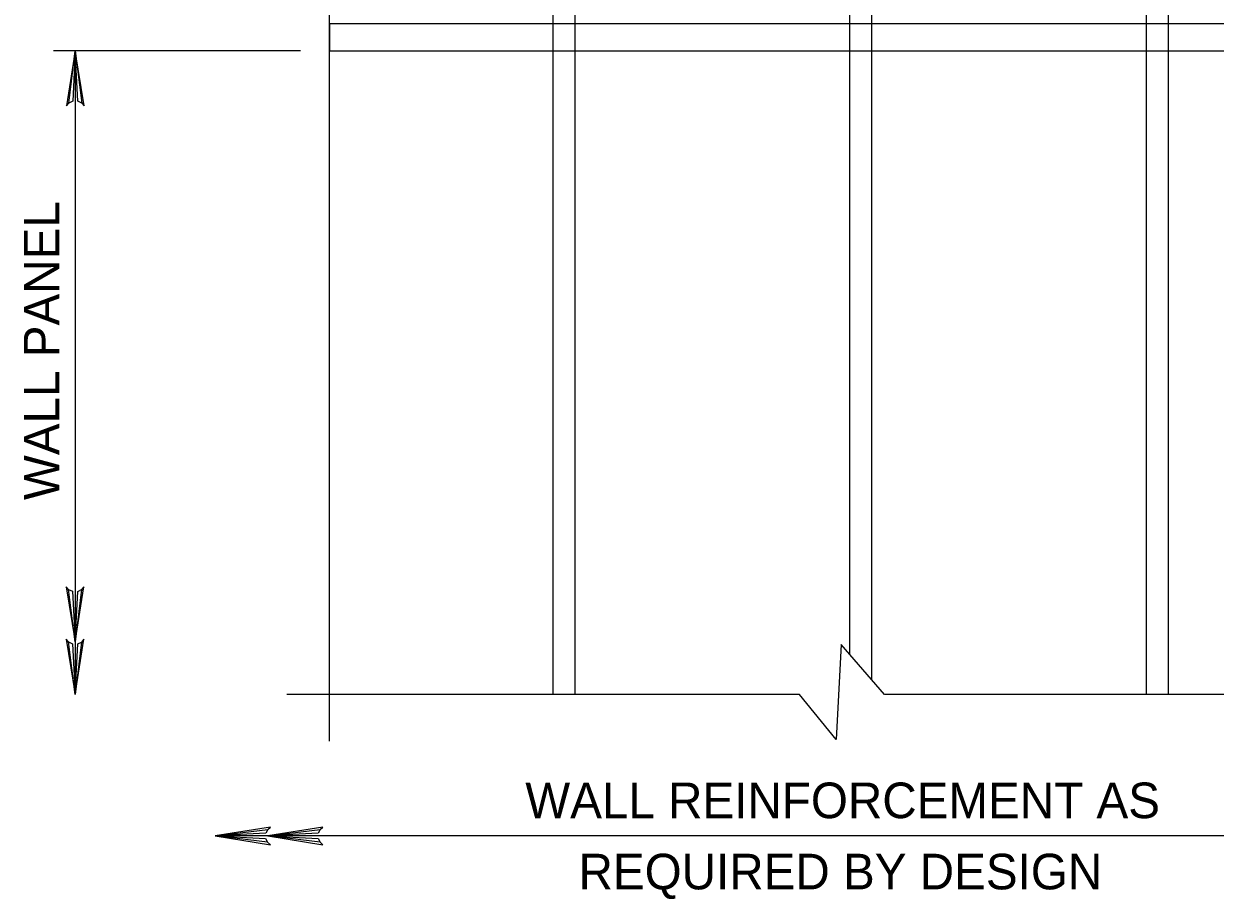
# Model space of a CAD drawing. Extents: x 641328 to 643024, y 298283 to 300065.
# Drawn here: x 642558.5 to 642658.9, y 299585.6 to 299659.4 of the extents above; entities that cross this region are included whole.
import ezdxf

# ---------------------------------------------------------------- set-up
doc = ezdxf.new("R2010")
doc.units = 0
doc.layers.add('2', color=7, linetype='Continuous')
doc.layers.add('63', color=7, linetype='Continuous')

msp = doc.modelspace()

# ---------------------------------------------------------------- linework, layer by layer
at = {"layer": '2'}
for p, q in [((642584.3, 299598.94), (642584.3, 299679.4)), ((642603.12, 299675.03), (642603.12, 299602.89)), ((642604.97, 299675.03), (642604.97, 299602.89)), ((642628.12, 299675.03), (642628.12, 299606.29)), ((642629.97, 299675.03), (642629.97, 299604.14)), ((642653.12, 299675.03), (642653.12, 299602.89)), ((642654.97, 299675.03), (642654.97, 299602.89)), ((642687.27, 299659.41), (642584.3, 299659.41)), ((642584.3, 299659.41), (642584.3, 299657.15)), ((642581.86, 299657.15), (642561.03, 299657.15)), ((642584.3, 299657.15), (642687.27, 299657.15)), ((642584.3, 299657.15), (642687.27, 299657.15)), ((642623.91, 299602.89), (642580.69, 299602.89)), ((642692.13, 299602.89), (642631.06, 299602.89))]:
    msp.add_line(p, q, dxfattribs=at)
at = {"layer": '63'}
for p, q in [((642562.86, 299657.15), (642562.86, 299602.89)), ((642627.41, 299607.11), (642626.99, 299599.08)), ((642631.06, 299602.89), (642627.41, 299607.11)), ((642626.99, 299599.08), (642623.91, 299602.89)), ((642679.97, 299590.96), (642574.65, 299590.96))]:
    msp.add_line(p, q, dxfattribs=at)
for points in [[(642563.41, 299652.72), (642563.09, 299652.89), (642562.86, 299657.15), (642563.41, 299652.72), (642563.61, 299652.49), (642562.86, 299657.15), (642562.65, 299652.89), (642562.33, 299652.73), (642562.86, 299657.15), (642562.12, 299652.49), (642562.33, 299652.73)], [(642562.3, 299611.74), (642562.62, 299611.58), (642562.86, 299607.31), (642562.3, 299611.74), (642562.11, 299611.97), (642562.86, 299607.31), (642563.07, 299611.57), (642563.38, 299611.73), (642562.86, 299607.31), (642563.6, 299611.97), (642563.38, 299611.73)], [(642562.3, 299607.31), (642562.62, 299607.15), (642562.86, 299602.89), (642562.3, 299607.31), (642562.11, 299607.54), (642562.86, 299602.89), (642563.07, 299607.15), (642563.38, 299607.3), (642562.86, 299602.89), (642563.6, 299607.54), (642563.38, 299607.3)], [(642579.08, 299591.51), (642578.92, 299591.19), (642574.65, 299590.96), (642579.08, 299591.51), (642579.31, 299591.71), (642574.65, 299590.96), (642578.91, 299590.75), (642579.07, 299590.43), (642574.65, 299590.96), (642579.31, 299590.22), (642579.07, 299590.43)], [(642583.51, 299591.51), (642583.34, 299591.19), (642579.08, 299590.96), (642583.51, 299591.51), (642583.74, 299591.71), (642579.08, 299590.96), (642583.34, 299590.75), (642583.5, 299590.43), (642579.08, 299590.96), (642583.74, 299590.22), (642583.5, 299590.43)]]:
    msp.add_lwpolyline(points, dxfattribs=at)

# ---------------------------------------------------------------- texts
at = {"layer": '2'}
for s, p in [('WALL REINFORCEMENT AS', (642600.79, 299592.46)), ('REQUIRED BY DESIGN', (642605.28, 299586.46))]:
    msp.add_text(s, height=3, dxfattribs=at).set_placement(p)
at = {"layer": '63'}
msp.add_text('WALL PANEL', height=3, rotation=90, dxfattribs=at).set_placement((642561.53, 299619.27))

doc.saveas('drawing.dxf')
